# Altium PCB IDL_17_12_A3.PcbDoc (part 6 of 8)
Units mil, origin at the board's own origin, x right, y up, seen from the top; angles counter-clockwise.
Board outline 5119.97 x 10350 mil, 6 copper layers (Top Signal, 3.3 Volt, GND, 5 Volt, Split Plane, Bot Signal), stack 66.2 mil thick; 510 components, 178 nets, 2317 pads, 385 vias.
Unrouted connection lines stored in the file: 1.
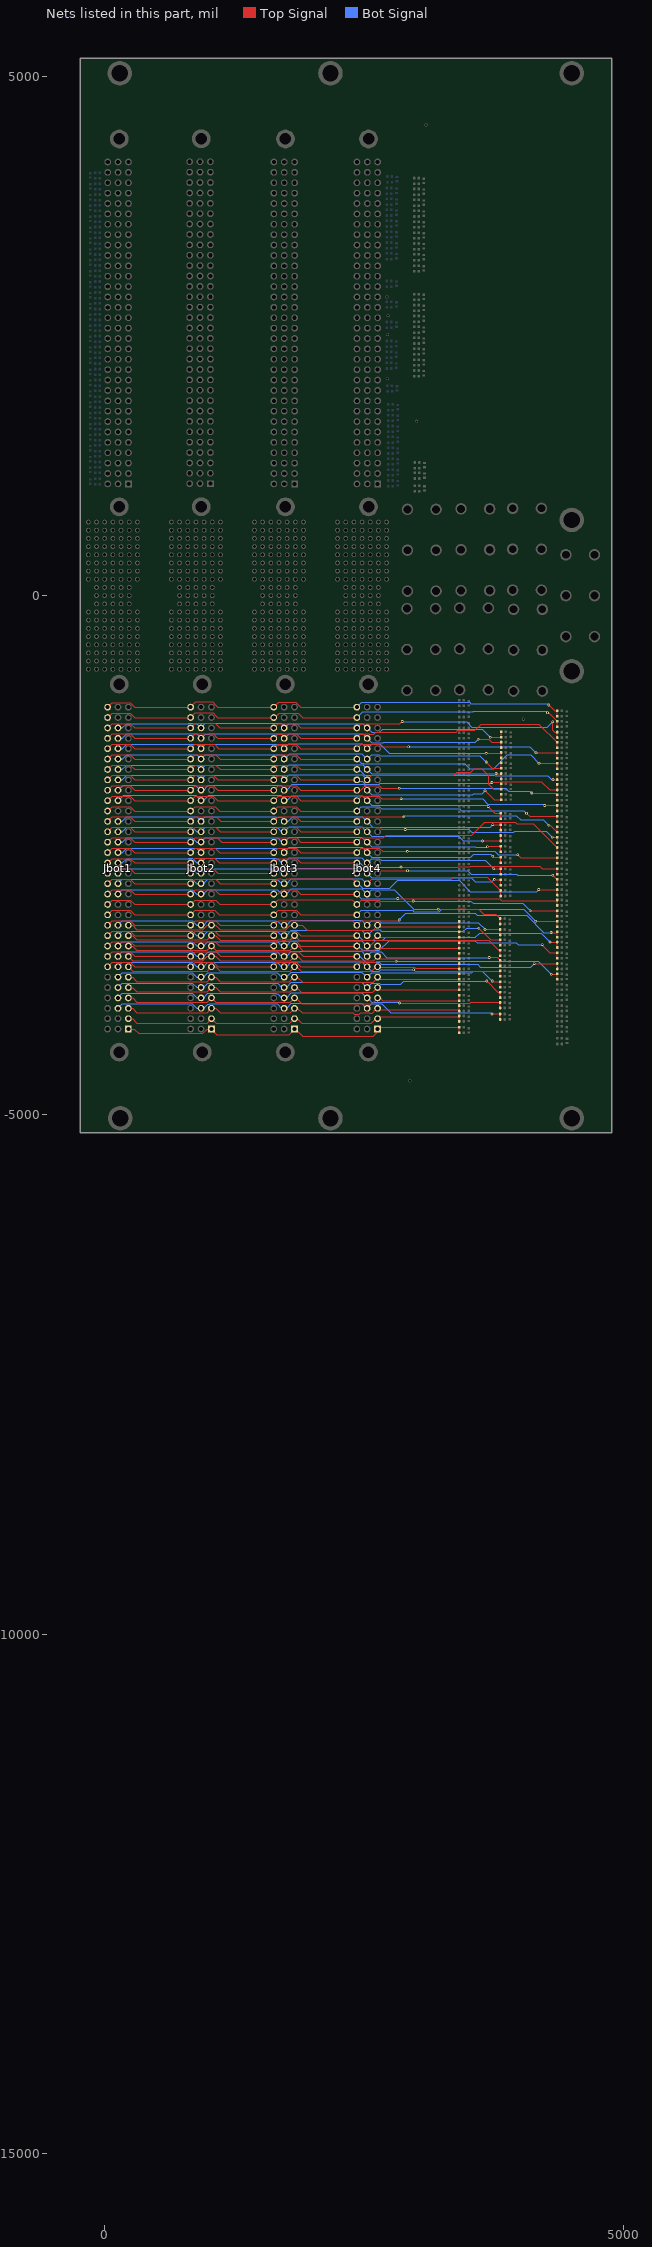
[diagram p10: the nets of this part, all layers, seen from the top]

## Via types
v1: diameter 25.59, hole 11.81, Top Signal to Bot Signal, 385 vias

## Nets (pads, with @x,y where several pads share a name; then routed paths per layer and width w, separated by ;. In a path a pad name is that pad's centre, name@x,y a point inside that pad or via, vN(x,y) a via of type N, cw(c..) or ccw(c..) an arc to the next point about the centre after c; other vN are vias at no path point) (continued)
JB22: Jbot1.A11 Jbot2.A11 Jbot3.A11 Jbot4.A11 R1RB_IDL_17_12_TerB22.1 R2RB_IDL_17_12_TerB22.2 | length 3346.2
  Top Signal w8: Jbot1.A11@228.26,-3173.77 228.68,-3173.35 268.12,-3173.35 310.6,-3215.83 945.79,-3215.83 988.27,-3173.35 Jbot2.A11@1028.19,-3173.35 1068.47,-3173.35 1111.37,-3216.25 1658.27,-3216.25 1658.55,-3215.97 1710.32,-3215.97 1710.59,-3216.25 1745.79,-3216.25 1788.27,-3173.77 Jbot3.A11@1828.19,-3173.77 1901.22,-3173.77 1949.03,-3221.58 2584.75,-3221.58 Jbot4.A11@2621.69,-3184.64 ; Jbot4.A11@2628.19,-3173.77 2644.59,-3190.17 R2RB_IDL_17_12_TerB22.2@3414.99,-3190.17 3414.99,-3164 3414.48,-3163.49 R1RB_IDL_17_12_TerB22.1@3414.48,-3137.31
JB23: Jbot1.A10 Jbot2.A10 Jbot3.A10 Jbot4.A10 R1RB_IDL_17_12_TerB23.1 R2RB_IDL_17_12_TerB23.2 | length 3421
  Top Signal w8: Jbot1.A10@228.26,-3273.77 268.54,-3273.77 310.6,-3315.83 985.71,-3315.83 Jbot2.A10@1028.19,-3273.35 1068.47,-3273.35 1111.37,-3316.25 1665.91,-3316.25 1666.19,-3315.97 1710.31,-3315.97 1710.59,-3316.25 1745.78,-3316.25 1746.06,-3315.97 1785.99,-3315.97 ; Jbot3.A10@1810.53,-3273.77 Jbot3.A10@1828.19,-3273.77 1785.99,-3315.97 ; Jbot3.A10@1828.19,-3277.46 1789.68,-3315.97 1785.99,-3315.97 ; Jbot3.A10@1828.19,-3277.42 1831.85,-3277.42 1874.33,-3319.9 2586.32,-3319.9 Jbot4.A10@2623.26,-3282.96 ; Jbot4.A10@2628.19,-3273.77 2644.59,-3290.17 R2RB_IDL_17_12_TerB23.2@3414.99,-3290.17 3414.99,-3264 3414.48,-3263.49 R1RB_IDL_17_12_TerB23.1@3414.48,-3237.31
JB24: Jbot1.A9 Jbot2.A9 Jbot3.A9 Jbot4.A9 R1RB_IDL_17_12_TerB24.1 R2RB_IDL_17_12_TerB24.2 | length 3352.2
  Top Signal w8: Jbot1.A9@228.26,-3373.77 268.54,-3373.77 310.6,-3415.83 985.71,-3415.83 Jbot2.A9@1028.19,-3373.35 1071.09,-3416.25 1645.79,-3416.25 1646.06,-3415.97 1710.32,-3415.97 1710.59,-3416.25 1745.79,-3416.25 1746.06,-3415.97 1785.99,-3415.97 Jbot3.A9@1828.19,-3373.77 ; Jbot3.A9@1826.41,-3375.74 1828.19,-3375.74 1866.68,-3375.74 1909.16,-3418.22 2589.47,-3418.22 Jbot4.A9@2626.41,-3381.28 ; Jbot4.A9@2628.19,-3373.77 2649.59,-3395.17 R2RB_IDL_17_12_TerB24.2@3414.99,-3395.17 3414.99,-3342.82 R1RB_IDL_17_12_TerB24.1@3414.48,-3342.31
JB25: Jbot1.A8 Jbot2.A8 Jbot3.A8 Jbot4.A8 R1RB_IDL_17_12_TerB25.1 R2RB_IDL_17_12_TerB25.2 | length 3346
  Top Signal w8: Jbot1.A8@228.26,-3473.77 271.86,-3517.37 859.07,-3517.37 860.61,-3515.83 945.79,-3515.83 988.27,-3473.35 Jbot2.A8@1028.19,-3473.35 1068.47,-3473.35 1111.37,-3516.25 1785.71,-3516.25 Jbot3.A8@1828.19,-3473.77 1857.7,-3473.77 1901.22,-3517.29 2590.29,-3517.29 Jbot4.A8@2622.47,-3485.11 ; Jbot4.A8@2628.19,-3473.77 2649.59,-3495.17 R2RB_IDL_17_12_TerB25.2@3414.99,-3495.17 3414.99,-3469 3414.48,-3468.49 R1RB_IDL_17_12_TerB25.1@3414.48,-3442.31
JB26: Jbot1.A7 Jbot2.A7 Jbot3.A7 Jbot4.A7 R1RB_IDL_17_12_TerB26.1 R2RB_IDL_17_12_TerB26.2 | length 3352.2
  Top Signal w8: Jbot1.A7@228.26,-3573.77 270.32,-3615.83 985.71,-3615.83 Jbot2.A7@1028.19,-3573.35 1068.47,-3573.35 1111.37,-3616.25 1786.21,-3616.25 ; 1786.21,-3615.75 Jbot3.A7@1828.19,-3573.77 ; Jbot3.A7@1811.46,-3573.17 1828.19,-3573.17 1851.74,-3573.17 1894.82,-3616.25 2573.92,-3616.25 Jbot4.A7@2611.46,-3578.71 ; Jbot4.A7@2628.19,-3573.77 2634.86,-3580.44 2984.33,-3580.44 2992.49,-3588.6 3408.42,-3588.6 R2RB_IDL_17_12_TerB26.2@3414.99,-3595.17 3414.99,-3569 3414.48,-3568.49 R1RB_IDL_17_12_TerB26.1@3414.48,-3542.31
JB27: Jbot1.A6 Jbot2.A6 Jbot3.A6 Jbot4.A6 R1RB_IDL_17_12_TerB27.1 R2RB_IDL_17_12_TerB27.2 | length 3349.5
  Top Signal w8: Jbot1.A6@228.26,-3673.77 268.54,-3673.77 310.6,-3715.83 985.71,-3715.83 Jbot2.A6@1028.19,-3673.35 1068.47,-3673.35 1111.37,-3716.25 1779.57,-3716.25 1822.05,-3673.77 Jbot3.A6@1828.19,-3673.77 1854.81,-3673.77 1905.23,-3724.19 2585.53,-3724.19 Jbot4.A6@2622.47,-3687.25 ; Jbot4.A6@2628.19,-3673.77 2649.59,-3695.17 R2RB_IDL_17_12_TerB27.2@3414.99,-3695.17 3414.99,-3669 3414.48,-3668.49 R1RB_IDL_17_12_TerB27.1@3414.48,-3642.31
JB28: Jbot1.A5 Jbot2.A5 Jbot3.A5 Jbot4.A5 R1RB_IDL_17_12_TerB28.1 R2RB_IDL_17_12_TerB28.2 | length 3348.9
  Top Signal w8: Jbot1.A5@228.26,-3773.77 268.54,-3773.77 310.6,-3815.83 985.71,-3815.83 Jbot2.A5@1028.19,-3773.35 1068.47,-3773.35 1111.37,-3816.25 1785.71,-3816.25 Jbot3.A5@1823.5,-3778.46 ; Jbot3.A5@1814.61,-3778.46 Jbot3.A5@1823.5,-3778.46 ; Jbot3.A5@1828.19,-3773.77 Jbot3.A5@1823.5,-3778.46 ; Jbot4.A5@2614.61,-3784 2581.38,-3817.23 1893.66,-3817.23 1854.88,-3778.46 1828.19,-3778.46 Jbot3.A5@1823.5,-3778.46 ; Jbot4.A5@2628.19,-3773.77 2649.59,-3795.17 R2RB_IDL_17_12_TerB28.2@3414.99,-3795.17 3414.99,-3769 3414.48,-3768.49 R1RB_IDL_17_12_TerB28.1@3414.48,-3742.31
JB29: Jbot1.A4 Jbot2.A4 Jbot3.A4 Jbot4.A4 R1RB_IDL_17_12_TerB29.1 R2RB_IDL_17_12_TerB29.2 | length 3354
  Top Signal w8: Jbot1.A4@228.26,-3873.77 268.54,-3873.77 310.6,-3915.83 985.71,-3915.83 Jbot2.A4@1028.19,-3873.35 1071.09,-3916.25 1785.71,-3916.25 Jbot3.A4@1816.53,-3885.43 ; Jbot3.A4@1813.82,-3885.43 Jbot3.A4@1816.53,-3885.43 ; Jbot3.A4@1828.19,-3873.77 Jbot3.A4@1816.53,-3885.43 ; Jbot4.A4@2613.82,-3890.97 2576.88,-3927.91 1896.58,-3927.91 1854.1,-3885.43 1828.19,-3885.43 Jbot3.A4@1816.53,-3885.43 ; Jbot4.A4@2628.19,-3873.77 2652.24,-3873.77 2678.64,-3900.17 R2RB_IDL_17_12_TerB29.2@3414.99,-3900.17 3414.99,-3874 3414.48,-3873.49 R1RB_IDL_17_12_TerB29.1@3414.48,-3847.31
JB30: Jbot1.A3 Jbot2.A3 Jbot3.A3 Jbot4.A3 R1RB_IDL_17_12_TerB30.1 R2RB_IDL_17_12_TerB30.2 | length 3373.1
  Top Signal w8: Jbot1.A3@228.26,-3973.77 268.54,-3973.77 310.6,-4015.83 985.71,-4015.83 Jbot2.A3@1028.19,-3973.35 1068.47,-3973.35 1111.37,-4016.25 1645.79,-4016.25 1647.24,-4014.79 1709.14,-4014.79 1710.59,-4016.25 1785.71,-4016.25 Jbot3.A3@1828.19,-3973.77 ; Jbot3.A3@1816.18,-3971.95 1828.19,-3971.95 1856.46,-3971.95 1901.8,-4017.29 2391.51,-4017.29 2405.51,-4031.29 2450.87,-4031.29 2464.87,-4017.29 2551.58,-4017.29 2553.27,-4018.98 2574.69,-4018.98 Jbot4.A3@2616.18,-3977.49 ; Jbot4.A3@2628.19,-3973.77 2641.29,-3986.87 3398.93,-3986.87 3413.61,-4001.55 3414.48,-4002.42 3414.48,-4000.17 R1RB_IDL_17_12_TerB30.1@3414.48,-3947.31
JB31: Jbot1.A2 Jbot2.A2 Jbot3.A2 Jbot4.A2 R1RB_IDL_17_12_TerB31.1 R2RB_IDL_17_12_TerB31.2 | length 3359.2
  Top Signal w8: Jbot1.A2@228.26,-4073.77 268.54,-4073.77 310.6,-4115.83 985.71,-4115.83 Jbot2.A2@1028.19,-4073.35 1072.13,-4117.29 1784.67,-4117.29 Jbot3.A2@1828.19,-4073.77 ; Jbot3.A2@1809.89,-4071.05 1828.19,-4071.05 1850.17,-4071.05 1896.4,-4117.29 2391.51,-4117.29 2393.61,-4119.39 2567.09,-4119.39 Jbot4.A2@2609.89,-4076.59 ; Jbot4.A2@2628.19,-4073.77 2647,-4054.96 3406.83,-4054.96 R1RB_IDL_17_12_TerB31.1@3414.48,-4047.31 3414.48,-4073.49 3414.99,-4074 R2RB_IDL_17_12_TerB31.2@3414.99,-4100.17
JB32: Jbot1.A1 Jbot2.A1 Jbot3.A1 Jbot4.A1 R1RB_IDL_17_12_TerB32.1 R2RB_IDL_17_12_TerB32.2 | length 3365.2
  Top Signal w8: Jbot1.A1@228.26,-4173.77 228.68,-4173.35 287.14,-4173.35 329.62,-4215.83 945.79,-4215.83 988.27,-4173.35 Jbot2.A1@1028.19,-4173.35 1081.65,-4226.8 1775.15,-4226.8 Jbot3.A1@1828.19,-4173.77 1838.04,-4173.77 1906.8,-4242.53 2587.11,-4242.53 Jbot4.A1@2624.05,-4205.59 ; Jbot4.A1@2628.19,-4173.77 2645.58,-4156.37 R1RB_IDL_17_12_TerB32.1@3414.08,-4156.37 3414.08,-4183.49 3414.59,-4184 R2RB_IDL_17_12_TerB32.2@3414.59,-4209.23
JB33: Jbot1.B30 Jbot2.B30 Jbot3.B30 Jbot4.B30 R1RB_IDL_17_12_TerB33.1 R2RB_IDL_17_12_TerB33.2 | length 3931.8
  Top Signal w8: v1(3713.46,-1362.75) R2RB_IDL_17_12_TerB33.2@3818.94,-1362.75 3818.94,-1337.23 3818.43,-1336.72 R1RB_IDL_17_12_TerB33.1@3818.43,-1309.89
  Bot Signal w8: Jbot1.B30@128.26,-1273.77 168.18,-1273.77 210.66,-1231.29 810.17,-1231.29 810.59,-1230.87 845.79,-1230.87 846.21,-1231.29 886.13,-1231.29 Jbot2.B30@928.19,-1273.35 970.67,-1230.87 1702.32,-1230.87 Jbot3.B30@1736.7,-1265.25 ; Jbot3.B30@1728.19,-1273.77 Jbot3.B30@1736.7,-1265.25 ; Jbot3.B30@1747.6,-1276.15 Jbot3.B30@1736.7,-1265.25 ; v1(3713.46,-1362.75) 3636.95,-1286.23 2675.8,-1286.23 2645.79,-1316.25 2570.67,-1316.25 Jbot4.B30@2528.19,-1273.77 2485.71,-1231.29 1770.67,-1231.29 Jbot3.B30@1736.7,-1265.25
JB34: Jbot1.B29 Jbot2.B29 Jbot3.B29 Jbot4.B29 R1RB_IDL_17_12_TerB34.1 R2RB_IDL_17_12_TerB34.2 | length 3900.6
  Top Signal w8: v1(3595.9,-1382.59) 3698.31,-1382.59 3725.61,-1409.89 R1RB_IDL_17_12_TerB34.1@3818.43,-1409.89 3818.43,-1436.72 3818.94,-1437.23 R2RB_IDL_17_12_TerB34.2@3818.94,-1462.75
  Bot Signal w8: Jbot1.B29@128.26,-1373.77 168.18,-1373.77 210.66,-1331.29 810.17,-1331.29 810.59,-1330.87 845.79,-1330.87 846.21,-1331.29 886.13,-1331.29 Jbot2.B29@928.19,-1373.35 967.45,-1334.09 1007.37,-1334.09 1010.59,-1330.87 1702.32,-1330.87 1736.7,-1365.25 Jbot3.B29@1737.89,-1366.44 ; Jbot3.B29@1728.19,-1373.77 1730.57,-1373.77 Jbot3.B29@1737.89,-1366.44 ; v1(3595.9,-1382.59) 3569.09,-1409.41 2687.15,-1409.41 2680.32,-1416.25 2570.67,-1416.25 Jbot4.B29@2528.19,-1373.77 2483.41,-1328.98 1775.35,-1328.98 Jbot3.B29@1737.89,-1366.44
JB35: Jbot1.B28 Jbot2.B28 Jbot3.B28 Jbot4.B28 R1RB_IDL_17_12_TerB35.1 R2RB_IDL_17_12_TerB35.2 | length 3917.6
  Top Signal w8: v1(3675.37,-1518.85) 3809.47,-1518.85 R1RB_IDL_17_12_TerB35.1@3818.43,-1509.89 3818.43,-1536.72 3818.94,-1537.23 R2RB_IDL_17_12_TerB35.2@3818.94,-1562.75
  Bot Signal w8: Jbot1.B28@128.26,-1473.77 168.18,-1473.77 210.66,-1431.29 810.17,-1431.29 810.59,-1430.87 845.79,-1430.87 846.21,-1431.29 886.13,-1431.29 Jbot2.B28@928.19,-1473.35 970.67,-1430.87 1645.36,-1430.87 1648.58,-1434.09 1705.54,-1434.09 Jbot3.B28@1734.67,-1463.22 ; Jbot3.B28@1728.19,-1473.77 1728.19,-1469.7 Jbot3.B28@1734.67,-1463.22 ; v1(3675.37,-1518.85) 2740.18,-1518.85 2651.58,-1430.25 2571.71,-1430.25 Jbot4.B28@2528.19,-1473.77 2479.01,-1424.59 1773.3,-1424.59 Jbot3.B28@1734.67,-1463.22
JB36: Jbot1.B27 Jbot2.B27 Jbot3.B27 Jbot4.B27 R1RB_IDL_17_12_TerB36.1 R2RB_IDL_17_12_TerB36.2 | length 3936.3
  Top Signal w8: v1(3673.33,-1602.57) 3733.51,-1662.75 R2RB_IDL_17_12_TerB36.2@3818.94,-1662.75 3818.94,-1637.23 3818.43,-1636.72 R1RB_IDL_17_12_TerB36.1@3818.43,-1609.89
  Bot Signal w8: Jbot1.B27@128.26,-1573.77 168.18,-1573.77 210.66,-1531.29 810.17,-1531.29 810.59,-1530.87 845.79,-1530.87 846.21,-1531.29 886.13,-1531.29 Jbot2.B27@928.19,-1573.35 970.67,-1530.87 1645.36,-1530.87 1648.58,-1534.09 1705.54,-1534.09 1736.7,-1565.25 Jbot3.B27@1738.96,-1567.51 ; Jbot3.B27@1728.19,-1573.77 1732.71,-1573.77 Jbot3.B27@1738.96,-1567.51 ; v1(3673.33,-1602.57) 3613.96,-1543.2 2657.7,-1543.2 2645.79,-1531.29 2570.67,-1531.29 Jbot4.B27@2528.19,-1573.77 2478.03,-1523.61 1782.86,-1523.61 Jbot3.B27@1738.96,-1567.51
JB37: Jbot1.B26 Jbot2.B26 Jbot3.B26 Jbot4.B26 R1RB_IDL_17_12_TerB37.1 R2RB_IDL_17_12_TerB37.2 | length 3878.4
  Top Signal w8: v1(3769.41,-1712.89) R1RB_IDL_17_12_TerB37.1@3818.43,-1712.89 3818.43,-1739.72 3818.94,-1740.23 R2RB_IDL_17_12_TerB37.2@3818.94,-1765.75
  Bot Signal w8: Jbot1.B26@128.26,-1673.77 168.18,-1673.77 210.66,-1631.29 810.17,-1631.29 810.59,-1630.87 845.79,-1630.87 846.21,-1631.29 886.13,-1631.29 Jbot2.B26@928.19,-1673.35 967.45,-1634.09 1007.37,-1634.09 1010.59,-1630.87 1702.32,-1630.87 1736.7,-1665.25 Jbot3.B26@1739.16,-1667.7 ; Jbot3.B26@1728.19,-1673.77 1733.1,-1673.77 Jbot3.B26@1739.16,-1667.7 ; v1(3769.41,-1712.89) 3769.1,-1713.2 3602.64,-1713.2 3601.56,-1714.28 3582.68,-1714.28 3581.61,-1713.2 2648.83,-1713.2 2645.79,-1716.25 2570.67,-1716.25 Jbot4.B26@2528.19,-1673.77 2484.57,-1630.14 1776.72,-1630.14 Jbot3.B26@1739.16,-1667.7
JB38: Jbot1.B25 Jbot2.B25 Jbot3.B25 Jbot4.B25 R1RB_IDL_17_12_TerB38.1 R2RB_IDL_17_12_TerB38.2 | length 4055.4
  Top Signal w8: Jbot4.B25@2528.19,-1773.77 2571.71,-1730.25 3363.75,-1730.25 3394,-1700 3527,-1700 3560,-1667 3630.02,-1667 3699.4,-1736.38 3699.4,-1816.9 3748.25,-1865.75 R2RB_IDL_17_12_TerB38.2@3818.94,-1865.75 3818.94,-1840.23 3818.43,-1839.72 R1RB_IDL_17_12_TerB38.1@3818.43,-1812.89 R1RB_IDL_17_12_TerB38.1@3812.84,-1818.47
  Bot Signal w8: Jbot1.B25@128.26,-1773.77 168.18,-1773.77 211.08,-1730.87 845.79,-1730.87 846.63,-1731.71 886.56,-1731.71 Jbot2.B25@928.19,-1773.35 970.67,-1730.87 1702.32,-1730.87 Jbot3.B25@1736.7,-1765.25 ; Jbot3.B25@1728.19,-1773.77 Jbot3.B25@1736.7,-1765.25 ; Jbot3.B25@1747.6,-1776.15 Jbot3.B25@1736.7,-1765.25 ; Jbot4.B25@2528.19,-1773.77 2481.16,-1726.74 1775.22,-1726.74 Jbot3.B25@1736.7,-1765.25
JB39: Jbot1.B24 Jbot2.B24 Jbot3.B24 Jbot4.B24 R1RB_IDL_17_12_TerB39.1 R2RB_IDL_17_12_TerB39.2 | length 3934.5
  Top Signal w8: v1(3662.95,-1878.23) 3750.46,-1965.75 R2RB_IDL_17_12_TerB39.2@3818.94,-1965.75 3818.94,-1940.23 3818.43,-1939.72 R1RB_IDL_17_12_TerB39.1@3818.43,-1912.89
  Bot Signal w8: Jbot1.B24@128.26,-1873.77 177.27,-1824.76 874.23,-1824.76 922.82,-1873.35 Jbot2.B24@928.19,-1873.35 ; Jbot2.B24@947.67,-1876.57 996.68,-1827.55 1693.64,-1827.55 1734.02,-1867.94 1742.23,-1876.15 Jbot3.B24@1747.6,-1876.15 ; Jbot3.B24@1756.27,-1867.32 1805.28,-1818.31 2492.85,-1818.31 2538.25,-1863.7 2541.45,-1866.9 Jbot4.B24@2556.2,-1866.9 ; Jbot4.B24@2528.19,-1873.77 2570.67,-1916.25 3545.64,-1916.25 3554.48,-1907.4 3633.78,-1907.4 v1(3662.95,-1878.23)
JB40: Jbot1.B23 Jbot2.B23 Jbot3.B23 Jbot4.B23 R1RB_IDL_17_12_TerB40.1 R2RB_IDL_17_12_TerB40.2 | length 3914.2
  Top Signal w8: v1(3693.95,-2031.23) 3757.26,-2094.54 R1RB_IDL_17_12_TerB40.1@3813.43,-2094.54 3813.43,-2120.72 3813.94,-2121.23 R2RB_IDL_17_12_TerB40.2@3813.94,-2147.4
  Bot Signal w8: Jbot1.B23@128.26,-1973.77 131.98,-1973.77 185.14,-1920.6 875.44,-1920.6 Jbot2.B23@928.19,-1973.35 ; Jbot2.B23@947.67,-1976.57 951.38,-1976.57 1004.55,-1923.4 1694.85,-1923.4 1736.7,-1965.25 Jbot3.B23@1745.22,-1973.77 ; Jbot3.B23@1728.19,-1973.77 Jbot3.B23@1745.22,-1973.77 ; v1(3693.95,-2031.23) 3681.99,-2019.28 2653.58,-2019.28 2651.58,-2017.29 2604.8,-2017.29 2602.8,-2019.28 2573.7,-2019.28 Jbot4.B23@2528.19,-1973.77 2479.95,-1925.52 1801.78,-1925.52 1753.54,-1973.77 Jbot3.B23@1745.22,-1973.77
JB41: Jbot1.B21 Jbot2.B21 Jbot3.B21 Jbot4.B21 R1RB_IDL_17_12_TerB41.1 R2RB_IDL_17_12_TerB41.2 | length 3897.4
  Top Signal w8: v1(3737.06,-2204.54) R1RB_IDL_17_12_TerB41.1@3813.43,-2204.54 3813.43,-2230.72 3813.94,-2231.23 R2RB_IDL_17_12_TerB41.2@3813.94,-2257.4
  Bot Signal w8: Jbot1.B21@128.26,-2173.77 168.18,-2173.77 210.66,-2131.29 810.17,-2131.29 810.59,-2130.87 885.71,-2130.87 Jbot2.B21@928.19,-2173.35 970.67,-2130.87 1645.36,-2130.87 1648.16,-2133.67 1705.12,-2133.67 1736.7,-2165.25 Jbot3.B21@1745.22,-2173.77 ; Jbot3.B21@1728.19,-2173.77 Jbot3.B21@1745.22,-2173.77 ; Jbot3.B21@1747.6,-2176.15 Jbot3.B21@1745.22,-2173.77 ; v1(3737.06,-2204.54) 3712.85,-2228.76 3554.8,-2228.76 3554.73,-2228.69 2583.11,-2228.69 Jbot4.B21@2528.19,-2173.77 2523.95,-2173.77 2481.47,-2131.29 1810.59,-2131.29 1768.11,-2173.77 Jbot3.B21@1745.22,-2173.77
JB42: Jbot1.B20 Jbot2.B20 Jbot3.B20 Jbot4.B20 R1RB_IDL_17_12_TerB42.1 R2RB_IDL_17_12_TerB42.2 | length 3936.9
  Top Signal w8: v1@3634.12,-2362.4 v1(3638.93,-2362.4) R2RB_IDL_17_12_TerB42.2@3813.94,-2362.4 3813.94,-2336.23 3813.43,-2335.72 R1RB_IDL_17_12_TerB42.1@3813.43,-2309.54
  Bot Signal w8: Jbot1.B20@128.26,-2273.77 168.18,-2273.77 210.66,-2231.29 810.17,-2231.29 810.59,-2230.87 845.79,-2230.87 888.27,-2273.35 Jbot2.B20@928.19,-2273.35 970.67,-2230.87 1662.39,-2230.87 1707.67,-2276.15 1728.19,-2276.15 Jbot3.B20@1747.6,-2276.15 ; Jbot3.B20@1728.19,-2273.77 1777.12,-2224.84 2438.18,-2224.84 ; 2438.6,-2224.42 2473.8,-2224.42 2516.28,-2266.9 2528.19,-2266.9 Jbot4.B20@2556.2,-2266.9 ; Jbot4.B20@2528.19,-2273.77 2571.42,-2317 3410,-2317 3455.4,-2362.4 v1(3638.93,-2362.4)
JB43: Jbot1.B19 Jbot2.B19 Jbot3.B19 Jbot4.B19 R1RB_IDL_17_12_TerB43.1 R2RB_IDL_17_12_TerB43.2 | length 3916.9
  Top Signal w8: v1(3685.78,-2417.56) 3688.79,-2414.54 R1RB_IDL_17_12_TerB43.1@3813.43,-2414.54 3813.43,-2440.72 3813.94,-2441.23 R2RB_IDL_17_12_TerB43.2@3813.94,-2467.4
  Bot Signal w8: Jbot1.B19@128.26,-2373.77 168.18,-2373.77 210.66,-2331.29 810.17,-2331.29 810.59,-2330.87 845.79,-2330.87 888.27,-2373.35 Jbot2.B19@928.19,-2373.35 970.67,-2330.87 1645.36,-2330.87 1648.16,-2333.67 1665.19,-2333.67 1707.67,-2376.15 1728.19,-2376.15 Jbot3.B19@1747.6,-2376.15 ; Jbot3.B19@1728.19,-2373.77 1777.12,-2324.84 2438.18,-2324.84 ; 2438.6,-2324.42 2473.8,-2324.42 2516.28,-2366.9 2528.19,-2366.9 Jbot4.B19@2556.2,-2366.9 ; Jbot4.B19@2528.19,-2373.77 2571.42,-2417 3569.86,-2417 3573.63,-2420.76 3682.57,-2420.76 v1(3685.78,-2417.56)
JB44: Jbot1.B18 Jbot2.B18 Jbot3.B18 Jbot4.B18 R1RB_IDL_17_12_TerB44.1 R2RB_IDL_17_12_TerB44.2 | length 3896
  Top Signal w8: v1(3737.1,-2508.99) 3747.65,-2519.54 R1RB_IDL_17_12_TerB44.1@3813.43,-2519.54 3813.43,-2545.72 3813.94,-2546.23 R2RB_IDL_17_12_TerB44.2@3813.94,-2572.4
  Bot Signal w8: Jbot1.B18@128.26,-2473.77 168.18,-2473.77 210.66,-2431.29 810.17,-2431.29 810.59,-2430.87 845.79,-2430.87 846.21,-2431.29 886.13,-2431.29 Jbot2.B18@928.19,-2473.35 967.45,-2434.09 1007.37,-2434.09 1010.59,-2430.87 1702.32,-2430.87 Jbot3.B18@1736.7,-2465.25 ; Jbot3.B18@1728.19,-2473.77 Jbot3.B18@1736.7,-2465.25 ; 2438.18,-2424.84 1777.12,-2424.84 Jbot3.B18@1736.7,-2465.25 ; 2438.6,-2424.42 2473.8,-2424.42 ; 2474.22,-2424.84 2479.26,-2424.84 Jbot4.B18@2528.19,-2473.77 2571.71,-2517.28 3524.72,-2517.28 3553,-2489 3717.1,-2489 v1(3737.1,-2508.99)
JB45: Jbot1.B17 Jbot2.B17 Jbot3.B17 Jbot4.B17 R1RB_IDL_17_12_TerB45.1 R2RB_IDL_17_12_TerB45.2 | length 3913.2
  Top Signal w8: v1(3746.62,-2629.54) R1RB_IDL_17_12_TerB45.1@3813.43,-2629.54 3813.43,-2655.72 3813.94,-2656.23 R2RB_IDL_17_12_TerB45.2@3813.94,-2682.4
  Bot Signal w8: Jbot1.B17@128.26,-2573.77 168.18,-2573.77 210.66,-2531.29 810.17,-2531.29 810.59,-2530.87 845.79,-2530.87 888.27,-2573.35 Jbot2.B17@928.19,-2573.35 970.67,-2530.87 1645.36,-2530.87 1648.16,-2533.67 1665.19,-2533.67 1707.67,-2576.15 1728.19,-2576.15 Jbot3.B17@1747.6,-2576.15 ; Jbot3.B17@1728.19,-2573.77 1777.12,-2524.84 2438.18,-2524.84 ; 2438.6,-2524.42 2473.8,-2524.42 Jbot4.B17@2516.28,-2566.9 ; Jbot4.B17@2528.19,-2573.77 2570.67,-2531.29 2645.79,-2531.29 2663.24,-2548.74 3665.82,-2548.74 v1(3746.62,-2629.54)
JB46: Jbot1.B16 Jbot2.B16 Jbot3.B16 Jbot4.B16 R1RB_IDL_17_12_TerB46.1 R2RB_IDL_17_12_TerB46.2 | length 3891.4
  Top Signal w8: v1(3753.11,-2732.44) 3755.22,-2734.54 R1RB_IDL_17_12_TerB46.1@3813.43,-2734.54 3813.43,-2760.72 3813.94,-2761.23 R2RB_IDL_17_12_TerB46.2@3813.94,-2787.4
  Bot Signal w8: Jbot1.B16@128.26,-2673.77 171.16,-2630.87 845.79,-2630.87 888.27,-2673.35 Jbot2.B16@928.19,-2673.35 ; Jbot2.B16@947.67,-2676.57 990.57,-2633.67 1007.79,-2633.67 1010.59,-2630.87 1662.39,-2630.87 1707.67,-2676.15 1728.19,-2676.15 Jbot3.B16@1747.6,-2676.15 ; Jbot3.B16@1756.27,-2667.32 1799.17,-2624.42 2473.8,-2624.42 2516.28,-2666.9 2528.19,-2666.9 Jbot4.B16@2556.2,-2666.9 ; Jbot4.B16@2528.19,-2673.77 2571.71,-2717.28 3531.64,-2717.28 3569.98,-2755.62 3582.02,-2755.62 3582.68,-2756.28 3729.27,-2756.28 v1(3753.11,-2732.44)
JB47: Jbot1.B15 Jbot2.B15 Jbot3.B15 Jbot4.B15 R1RB_IDL_17_12_TerB47.1 R2RB_IDL_17_12_TerB47.2 | length 3926
  Top Signal w8: Jbot4.B15@2528.19,-2773.77 2571.71,-2730.25 3339.75,-2730.25 3359,-2711 3582.37,-2711 3582.68,-2710.69 3601.56,-2710.69 3601.88,-2711 3684.88,-2711 R1RB_IDL_17_12_TerB47.1@3813.43,-2839.54 3813.43,-2865.72 3813.94,-2866.23 R2RB_IDL_17_12_TerB47.2@3813.94,-2892.4
  Bot Signal w8: Jbot1.B15@128.26,-2773.77 171.16,-2730.87 845.79,-2730.87 888.27,-2773.35 Jbot2.B15@928.19,-2773.35 ; Jbot2.B15@947.67,-2776.57 993.37,-2730.87 1645.36,-2730.87 1648.16,-2733.67 1665.19,-2733.67 1707.67,-2776.15 1728.19,-2776.15 Jbot3.B15@1747.6,-2776.15 ; Jbot3.B15@1756.27,-2767.32 1799.17,-2724.42 2473.8,-2724.42 2516.28,-2766.9 2528.19,-2766.9 Jbot4.B15@2556.2,-2766.9
JB48: Jbot1.B14 Jbot2.B14 Jbot3.B14 Jbot4.B14 R1RB_IDL_17_12_TerB48.1 R2RB_IDL_17_12_TerB48.2 | length 3937.4
  Top Signal w8: v1(3211.55,-3019.26) 3399.24,-3019.26 3401.98,-3016.51 3470.39,-3016.51 3473.02,-3019.15 3603.82,-3019.15 3651.13,-3066.45 3765.33,-3066.45 R1RB_IDL_17_12_TerB48.1@3808.43,-3109.54 3808.43,-3135.72 3808.94,-3136.23 R2RB_IDL_17_12_TerB48.2@3808.94,-3162.4
  Bot Signal w8: Jbot1.B14@128.26,-2873.77 171.16,-2830.87 845.79,-2830.87 888.27,-2873.35 Jbot2.B14@928.19,-2873.35 ; Jbot2.B14@947.67,-2876.57 990.57,-2833.67 1007.79,-2833.67 1010.59,-2830.87 1662.39,-2830.87 1707.67,-2876.15 1728.19,-2876.15 Jbot3.B14@1747.6,-2876.15 ; Jbot3.B14@1756.27,-2867.32 1799.17,-2824.42 2473.8,-2824.42 Jbot4.B14@2516.28,-2866.9 ; Jbot4.B14@2528.19,-2873.77 2569.87,-2832.08 2609.8,-2832.08 2610.59,-2831.29 2645.79,-2831.29 2646.58,-2832.08 2752.91,-2832.08 2753.71,-2831.29 2787.48,-2831.29 2975.46,-3019.26 v1(3211.55,-3019.26)
JB49: Jbot1.B11 Jbot2.B11 Jbot3.B11 Jbot4.B11 R1RB_IDL_17_12_TerB49.1 R2RB_IDL_17_12_TerB49.2 | length 3872.5
  Top Signal w8: v1(3663.26,-3214.54) R1RB_IDL_17_12_TerB49.1@3808.43,-3214.54 3808.43,-3240.72 3808.94,-3241.23 R2RB_IDL_17_12_TerB49.2@3808.94,-3267.4
  Bot Signal w8: Jbot1.B11@128.26,-3173.77 171.16,-3130.87 845.79,-3130.87 888.27,-3173.35 Jbot2.B11@928.19,-3173.35 ; Jbot2.B11@947.67,-3176.57 993.37,-3130.87 1645.36,-3130.87 1648.16,-3133.67 1665.19,-3133.67 1707.67,-3176.15 1728.19,-3176.15 Jbot3.B11@1747.6,-3176.15 ; Jbot3.B11@1756.27,-3167.32 1799.17,-3124.42 2473.8,-3124.42 2516.28,-3166.9 2528.19,-3166.9 Jbot4.B11@2535.06,-3166.9 ; Jbot4.B11@2528.19,-3173.77 Jbot4.B11@2535.06,-3166.9 ; v1(3663.26,-3214.54) 3599.69,-3150.98 2665.48,-3150.98 2645.79,-3131.29 2570.67,-3131.29 Jbot4.B11@2535.06,-3166.9
JB50: Jbot1.B10 Jbot2.B10 Jbot3.B10 Jbot4.B10 R1RB_IDL_17_12_TerB50.1 R2RB_IDL_17_12_TerB50.2 | length 3890.4
  Top Signal w8: v1(3603.95,-3202.23) 3716.26,-3314.54 R1RB_IDL_17_12_TerB50.1@3808.43,-3314.54 3808.43,-3340.72 3808.94,-3341.23 R2RB_IDL_17_12_TerB50.2@3808.94,-3367.4
  Bot Signal w8: Jbot1.B10@128.26,-3273.77 171.16,-3230.87 845.79,-3230.87 888.27,-3273.35 Jbot2.B10@928.19,-3273.35 ; Jbot2.B10@947.67,-3276.57 990.57,-3233.67 1007.79,-3233.67 1010.59,-3230.87 1662.39,-3230.87 1707.67,-3276.15 1728.19,-3276.15 Jbot3.B10@1747.6,-3276.15 ; Jbot3.B10@1756.27,-3267.32 1799.17,-3224.42 2473.8,-3224.42 Jbot4.B10@2516.28,-3266.9 ; Jbot4.B10@2528.19,-3273.77 2584.67,-3217.29 2651.58,-3217.29 2665.3,-3231 3455,-3231 3485.38,-3200.62 3602.33,-3200.62 v1(3603.95,-3202.23)
JB51: Jbot1.B9 Jbot2.B9 Jbot3.B9 Jbot4.B9 R1RB_IDL_17_12_TerB51.1 R2RB_IDL_17_12_TerB51.2 | length 3906.1
  Top Signal w8: Jbot4.B9@2528.19,-3373.77 2552.25,-3373.77 2609.77,-3316.25 3698.16,-3316.25 3796.46,-3414.54 R1RB_IDL_17_12_TerB51.1@3808.43,-3414.54 3808.43,-3466.89 R2RB_IDL_17_12_TerB51.2@3808.94,-3467.4
  Bot Signal w8: Jbot1.B9@128.26,-3373.77 171.16,-3330.87 845.79,-3330.87 888.27,-3373.35 Jbot2.B9@928.19,-3373.35 ; Jbot2.B9@947.67,-3376.57 993.37,-3330.87 1645.36,-3330.87 1648.16,-3333.67 1665.19,-3333.67 1707.67,-3376.15 1728.19,-3376.15 Jbot3.B9@1747.6,-3376.15 ; Jbot3.B9@1756.27,-3367.32 1799.17,-3324.42 2473.8,-3324.42 2516.28,-3366.9 2528.19,-3366.9 Jbot4.B9@2556.2,-3366.9
JB52: Jbot1.B8 Jbot2.B8 Jbot3.B8 Jbot4.B8 R1RB_IDL_17_12_TerB52.1 R2RB_IDL_17_12_TerB52.2 | length 3873.2
  Top Signal w8: v1(3702.71,-3484.23) 3780.12,-3484.23 R1RB_IDL_17_12_TerB52.1@3808.43,-3512.54 3808.43,-3538.72 3808.94,-3539.23 R2RB_IDL_17_12_TerB52.2@3808.94,-3565.4
  Bot Signal w8: Jbot1.B8@128.26,-3473.77 171.16,-3430.87 845.79,-3430.87 888.27,-3473.35 Jbot2.B8@928.19,-3473.35 ; Jbot2.B8@947.67,-3476.57 990.57,-3433.67 1007.79,-3433.67 1010.59,-3430.87 1662.39,-3430.87 1707.67,-3476.15 1728.19,-3476.15 Jbot3.B8@1747.6,-3476.15 ; Jbot3.B8@1756.27,-3467.32 1799.17,-3424.42 2473.8,-3424.42 2516.28,-3466.9 2528.19,-3466.9 Jbot4.B8@2535.06,-3466.9 ; Jbot4.B8@2528.19,-3473.77 Jbot4.B8@2535.06,-3466.9 ; v1(3702.71,-3484.23) 3700.83,-3486.11 2718.46,-3486.11 2663.64,-3431.29 2570.67,-3431.29 Jbot4.B8@2535.06,-3466.9
JB53: Jbot1.B7 Jbot2.B7 Jbot3.B7 Jbot4.B7 R1RB_IDL_17_12_TerB53.1 R2RB_IDL_17_12_TerB53.2 | length 3873.4
  Top Signal w8: v1(2974.89,-3603.23) 2990.34,-3618.69 2991.06,-3617.96 3803.01,-3617.96 R1RB_IDL_17_12_TerB53.1@3808.43,-3612.54 3808.43,-3638.72 3808.94,-3639.23 R2RB_IDL_17_12_TerB53.2@3808.94,-3665.4
  Bot Signal w8: Jbot1.B7@128.26,-3573.77 171.16,-3530.87 845.79,-3530.87 888.27,-3573.35 Jbot2.B7@928.19,-3573.35 ; Jbot2.B7@947.67,-3576.57 993.37,-3530.87 1645.36,-3530.87 1648.16,-3533.67 1665.19,-3533.67 1707.67,-3576.15 1728.19,-3576.15 Jbot3.B7@1747.6,-3576.15 ; Jbot3.B7@1756.27,-3567.32 1799.17,-3524.42 2473.8,-3524.42 2516.28,-3566.9 2528.19,-3566.9 Jbot4.B7@2556.2,-3566.9 ; Jbot4.B7@2528.19,-3573.77 2570.67,-3616.25 2645.79,-3616.25 2658.8,-3603.23 v1(2974.89,-3603.23)
JB54: Jbot1.B6 Jbot2.B6 Jbot3.B6 Jbot4.B6 R1RB_IDL_17_12_TerB54.1 R2RB_IDL_17_12_TerB54.2 | length 3885.1
  Top Signal w8: v1(3731.88,-3710.48) 3738.95,-3717.54 R1RB_IDL_17_12_TerB54.1@3808.43,-3717.54 3808.43,-3743.72 3808.94,-3744.23 R2RB_IDL_17_12_TerB54.2@3808.94,-3770.4
  Bot Signal w8: Jbot1.B6@128.26,-3673.77 171.16,-3630.87 845.79,-3630.87 888.27,-3673.35 Jbot2.B6@928.19,-3673.35 ; Jbot2.B6@947.67,-3676.57 990.57,-3633.67 1007.79,-3633.67 1010.59,-3630.87 1662.39,-3630.87 1707.67,-3676.15 1728.19,-3676.15 Jbot3.B6@1747.6,-3676.15 ; Jbot3.B6@1756.27,-3667.32 1799.17,-3624.42 2473.8,-3624.42 2516.28,-3666.9 2528.19,-3666.9 Jbot4.B6@2535.06,-3666.9 ; Jbot4.B6@2528.19,-3673.77 Jbot4.B6@2535.06,-3666.9 ; v1(3731.88,-3710.48) 3727.47,-3710.48 3635.68,-3618.69 3550.68,-3618.69 3536.88,-3632.49 2646.99,-3632.49 2645.79,-3631.29 2570.67,-3631.29 Jbot4.B6@2535.06,-3666.9
JB55: Jbot1.B5 Jbot2.B5 Jbot3.B5 Jbot4.B5 R1RB_IDL_17_12_TerB55.1 R2RB_IDL_17_12_TerB55.2 | length 3881
  Top Signal w8: v1(3678.88,-3710.48) 3785.95,-3817.54 R1RB_IDL_17_12_TerB55.1@3808.43,-3817.54 3808.43,-3843.72 3808.94,-3844.23 R2RB_IDL_17_12_TerB55.2@3808.94,-3870.4
  Bot Signal w8: Jbot1.B5@128.26,-3773.77 171.16,-3730.87 845.79,-3730.87 888.27,-3773.35 Jbot2.B5@928.19,-3773.35 ; Jbot2.B5@947.67,-3776.57 993.37,-3730.87 1645.36,-3730.87 1648.16,-3733.67 1665.19,-3733.67 1707.67,-3776.15 1728.19,-3776.15 Jbot3.B5@1747.6,-3776.15 ; Jbot3.B5@1756.27,-3767.32 1799.17,-3724.42 2473.8,-3724.42 Jbot4.B5@2516.28,-3766.9 ; Jbot4.B5@2528.19,-3773.77 2570.67,-3731.29 2645.79,-3731.29 2656.46,-3741.96 2851.29,-3741.96 2881.61,-3711.65 3677.71,-3711.65 v1(3678.88,-3710.48)
JB56: Jbot1.B4 Jbot2.B4 Jbot3.B4 Jbot4.B4 R1RB_IDL_17_12_TerB56.1 R2RB_IDL_17_12_TerB56.2 | length 3864.3
  Top Signal w8: v1(2839.37,-3923) v1(2839.37,-3923) 3518.55,-3922.96 3523.97,-3917.54 R1RB_IDL_17_12_TerB56.1@3808.43,-3917.54 3808.43,-3943.72 3808.94,-3944.23 R2RB_IDL_17_12_TerB56.2@3808.94,-3970.4
  Bot Signal w8: Jbot1.B4@128.26,-3873.77 171.16,-3830.87 845.79,-3830.87 888.27,-3873.35 Jbot2.B4@928.19,-3873.35 ; Jbot2.B4@947.67,-3876.57 993.37,-3830.87 1645.36,-3830.87 1648.16,-3833.67 1665.19,-3833.67 1707.67,-3876.15 1728.19,-3876.15 Jbot3.B4@1747.6,-3876.15 ; Jbot3.B4@1756.27,-3867.32 1799.17,-3824.42 2473.8,-3824.42 2516.28,-3866.9 2528.19,-3866.9 Jbot4.B4@2556.2,-3866.9 ; Jbot4.B4@2528.19,-3873.77 2570.67,-3916.25 2645.79,-3916.25 2645.92,-3916.11 2832.48,-3916.11 v1(2839.37,-3923)
JB57: Jbot1.B3 Jbot2.B3 Jbot3.B3 Jbot4.B3 R1RB_IDL_17_12_TerB57.1 R2RB_IDL_17_12_TerB57.2 | length 3860.4
  Top Signal w8: v1(3730.54,-4028.52) R1RB_IDL_17_12_TerB57.1@3808.39,-4028.52 3808.39,-4054.72 3808.9,-4055.23 R2RB_IDL_17_12_TerB57.2@3808.9,-4081.38
  Bot Signal w8: Jbot1.B3@128.26,-3973.77 171.16,-3930.87 845.79,-3930.87 888.27,-3973.35 Jbot2.B3@928.19,-3973.35 ; Jbot2.B3@947.67,-3976.57 990.57,-3933.67 1007.79,-3933.67 1010.59,-3930.87 1662.39,-3930.87 1707.67,-3976.15 1728.19,-3976.15 Jbot3.B3@1747.6,-3976.15 ; Jbot3.B3@1756.27,-3967.32 1799.17,-3924.42 2473.8,-3924.42 Jbot4.B3@2516.28,-3966.9 ; Jbot4.B3@2528.19,-3973.77 2571.71,-3930.25 2651.58,-3930.25 2651.72,-3930.11 2669.56,-3930.11 2756.45,-4017 3006.55,-4017 3719.02,-4017 v1(3730.54,-4028.52)
JB58: Jbot1.C32 Jbot2.C32 Jbot3.C32 Jbot4.C32 R1RB_IDL_17_12_TerB58.1 R2RB_IDL_17_12_TerB58.2 | length 4553.1
  Top Signal w8: Jbot1.C32@28.26,-1073.77 70.74,-1031.29 245.86,-1031.29 288.34,-1073.77 827.77,-1073.77 Jbot2.C32@828.19,-1073.35 877.91,-1023.62 1038.55,-1023.62 1070.67,-1055.75 1070.67,-1056.59 1087.85,-1073.77 Jbot3.C32@1628.19,-1073.77 1676.31,-1025.64 1840.14,-1025.64 1888.27,-1073.77 Jbot4.C32@2428.19,-1073.77 ; v1(4276.89,-1052.46) 4332.68,-1108.25 R1RB_IDL_17_12_TerB58.1@4358.16,-1108.25 4358.16,-1134.94 4358.67,-1135.46 R2RB_IDL_17_12_TerB58.2@4358.67,-1161.11
  Bot Signal w8: Jbot4.C32@2428.19,-1073.77 2474.96,-1027 3515,-1027 3527,-1039 4263.43,-1039 v1(4276.89,-1052.46)
JB59: Jbot1.C31 Jbot2.C31 Jbot3.C31 Jbot4.C31 R1RB_IDL_17_12_TerB59.1 R2RB_IDL_17_12_TerB59.2 | length 4554.9
  Top Signal w8: Jbot1.C31@28.26,-1173.77 70.74,-1131.29 245.86,-1131.29 288.34,-1173.77 827.77,-1173.77 Jbot2.C31@828.19,-1173.35 871.74,-1129.8 904.77,-1129.8 ; 904.8,-1129.83 951.58,-1129.83 ; 951.61,-1129.8 1044.72,-1129.8 1070.67,-1155.75 1070.67,-1156.59 1087.85,-1173.77 Jbot3.C31@1628.19,-1173.77 1637.41,-1173.77 1680.03,-1131.15 1863.81,-1131.15 1906.42,-1173.77 Jbot4.C31@2428.19,-1173.77 ; v1(4264.57,-1126.66) 4275.89,-1126.66 4357.48,-1208.25 R1RB_IDL_17_12_TerB59.1@4358.16,-1208.25 4358.16,-1234.94 4358.67,-1235.46 R2RB_IDL_17_12_TerB59.2@4358.67,-1261.11
  Bot Signal w8: Jbot4.C31@2428.19,-1173.77 2485.71,-1116.25 3547.64,-1116.25 3550.68,-1113.2 4251.12,-1113.2 v1(4264.57,-1126.66)
JB60: Jbot1.C30 Jbot2.C30 Jbot3.C30 Jbot4.C30 R1RB_IDL_17_12_TerB60.1 R2RB_IDL_17_12_TerB60.2 | length 4657.1
  Top Signal w8: Jbot1.C30@28.26,-1273.77 70.74,-1231.29 245.86,-1231.29 288.34,-1273.77 827.77,-1273.77 Jbot2.C30@828.19,-1273.35 871.71,-1229.83 1063.2,-1229.83 1107.14,-1273.77 Jbot3.C30@1628.19,-1273.77 1670.67,-1231.29 1845.78,-1231.29 1848.17,-1233.67 1888.27,-1273.77 Jbot4.C30@2428.19,-1273.77 2470.67,-1231.29 2545.78,-1231.29 2550.07,-1235.58 2606.3,-1235.58 2610.59,-1231.29 2645.78,-1231.29 2650.07,-1235.58 2840.49,-1235.58 v1(2864.83,-1211.24) ; v1(4314.68,-1213.46) 4314.68,-1295.25 4332.68,-1313.25 R1RB_IDL_17_12_TerB60.1@4358.16,-1313.25 4358.16,-1339.94 4358.67,-1340.46 R2RB_IDL_17_12_TerB60.2@4358.67,-1366.11
  Bot Signal w8: v1(2864.83,-1211.24) 2869.84,-1216.25 3486.78,-1216.25 3537.33,-1266.8 4261.34,-1266.8 v1(4314.68,-1213.46)
JB61: Jbot1.C29 Jbot2.C29 Jbot3.C29 Jbot4.C29 R1RB_IDL_17_12_TerB61.1 R2RB_IDL_17_12_TerB61.2 | length 4627.4
  Top Signal w8: Jbot1.C29@28.26,-1373.77 70.74,-1331.29 245.86,-1331.29 288.34,-1373.77 827.77,-1373.77 Jbot2.C29@828.19,-1373.35 872.13,-1329.4 904.37,-1329.4 904.8,-1329.83 951.58,-1329.83 952.01,-1329.4 1044.32,-1329.4 1070.67,-1355.75 1070.67,-1356.59 1087.85,-1373.77 Jbot3.C29@1628.19,-1373.77 1668.29,-1333.67 1708.21,-1333.67 1710.59,-1331.29 1845.79,-1331.29 1888.27,-1373.77 Jbot4.C29@2428.19,-1373.77 2428.19,-1363.63 2458.87,-1332.94 2508.94,-1332.94 2510.59,-1331.29 2545.79,-1331.29 2547.44,-1332.94 2592.44,-1332.94 2609.13,-1316.25 3384.25,-1316.25 3401.98,-1298.51 3565.77,-1298.51 3626.65,-1237.64 4182.56,-1237.64 R1RB_IDL_17_12_TerB61.1@4358.16,-1413.25 4358.67,-1413.76 R2RB_IDL_17_12_TerB61.2@4358.67,-1466.11
JB62: Jbot1.C28 Jbot2.C28 Jbot3.C28 Jbot4.C28 R1RB_IDL_17_12_TerB62.1 R2RB_IDL_17_12_TerB62.2 | length 4542.5
  Top Signal w8: Jbot1.C28@28.26,-1473.77 70.74,-1431.29 245.86,-1431.29 288.34,-1473.77 827.77,-1473.77 Jbot2.C28@828.19,-1473.35 869.19,-1432.35 909.11,-1432.35 910.59,-1430.87 1058.1,-1430.87 1101,-1473.77 Jbot3.C28@1628.19,-1473.77 1670.67,-1431.29 1845.78,-1431.29 1848.17,-1433.67 1888.27,-1473.77 Jbot4.C28@2428.19,-1473.77 2470.56,-1431.4 2510.48,-1431.4 2510.59,-1431.29 2545.79,-1431.29 2545.9,-1431.4 2610.48,-1431.4 2610.59,-1431.29 2645.79,-1431.29 2669.5,-1455 v1(2926.95,-1455) ; v1(4153.58,-1513.25) R1RB_IDL_17_12_TerB62.1@4358.16,-1513.25 4358.16,-1539.94 4358.67,-1540.46 R2RB_IDL_17_12_TerB62.2@4358.67,-1566.11
  Bot Signal w8: v1(2926.95,-1455) 3987.7,-1455 3990.1,-1452.61 4092.94,-1452.61 v1(4153.58,-1513.25)
JB63: Jbot1.C27 Jbot2.C27 Jbot3.C27 Jbot4.C27 R1RB_IDL_17_12_TerB63.1 R2RB_IDL_17_12_TerB63.2 | length 4614.9
  Top Signal w8: Jbot1.C27@28.26,-1573.77 70.74,-1531.29 245.86,-1531.29 288.34,-1573.77 827.77,-1573.77 Jbot2.C27@828.19,-1573.35 870.67,-1530.87 1067.85,-1530.87 1110.75,-1573.77 Jbot3.C27@1628.19,-1573.77 1668.29,-1533.67 1708.21,-1533.67 1710.59,-1531.29 1845.79,-1531.29 1888.27,-1573.77 Jbot4.C27@2428.19,-1573.77 ; v1(4181.8,-1613.25) R1RB_IDL_17_12_TerB63.1@4358.16,-1613.25 4358.16,-1639.94 4358.67,-1640.46 R2RB_IDL_17_12_TerB63.2@4358.67,-1666.11
  Bot Signal w8: Jbot4.C27@2428.19,-1573.77 2470.57,-1616.14 2490.37,-1616.14 2491.22,-1617 3469.41,-1617 3517.2,-1664.8 3745.59,-1664.8 3877.95,-1532.44 4100.99,-1532.44 v1(4181.8,-1613.25)
JB64: Jbot1.C26 Jbot2.C26 Jbot3.C26 Jbot4.C26 R1RB_IDL_17_12_TerB64.1 R2RB_IDL_17_12_TerB64.2 | length 4533.8
  Top Signal w8: Jbot1.C26@28.26,-1673.77 70.74,-1631.29 245.86,-1631.29 288.34,-1673.77 827.77,-1673.77 Jbot2.C26@828.19,-1673.35 870.67,-1630.87 1067.85,-1630.87 1110.75,-1673.77 Jbot3.C26@1628.19,-1673.77 1670.67,-1631.29 1845.79,-1631.29 1888.27,-1673.77 Jbot4.C26@2428.19,-1673.77 ; v1(4318.03,-1771.11) R2RB_IDL_17_12_TerB64.2@4358.67,-1771.11 4358.67,-1745.46 4358.16,-1744.94 R1RB_IDL_17_12_TerB64.1@4358.16,-1718.25
  Bot Signal w8: Jbot4.C26@2428.19,-1673.77 2447.99,-1673.77 2504.47,-1730.25 2651.58,-1730.25 2653.55,-1728.28 3549.61,-1728.28 3550.68,-1727.2 3569.56,-1727.2 3570.64,-1728.28 3607.36,-1728.28 3608.44,-1727.2 3751.49,-1727.2 3759.97,-1735.68 3778.86,-1735.68 3779.68,-1734.86 4268.72,-1734.86 4304.97,-1771.11 v1(4318.03,-1771.11)
JB65: Jbot1.C25 Jbot2.C25 Jbot3.C25 Jbot4.C25 R1RB_IDL_17_12_TerB65.1 R2RB_IDL_17_12_TerB65.2 | length 4551.4
  Top Signal w8: Jbot1.C25@28.26,-1773.77 70.74,-1731.29 245.86,-1731.29 288.34,-1773.77 827.77,-1773.77 Jbot2.C25@828.19,-1773.35 870.67,-1730.87 1045.78,-1730.87 1088.68,-1773.77 Jbot3.C25@1628.19,-1773.77 1668.29,-1733.67 1708.21,-1733.67 1710.59,-1731.29 1845.79,-1731.29 1888.27,-1773.77 Jbot4.C25@2428.19,-1773.77 ; v1(3728.75,-1798.89) 3797.14,-1798.89 3805.93,-1790.09 4204.67,-1790.09 4285.68,-1871.11 R2RB_IDL_17_12_TerB65.2@4358.67,-1871.11 4358.67,-1845.46 4358.16,-1844.94 R1RB_IDL_17_12_TerB65.1@4358.16,-1818.25
  Bot Signal w8: Jbot4.C25@2428.19,-1773.77 2442.83,-1788.41 2482.76,-1788.41 2510.59,-1816.25 2645.79,-1816.25 2655.59,-1806.44 3721.19,-1806.44 v1(3728.75,-1798.89)
JB66: Jbot1.C24 Jbot2.C24 Jbot3.C24 Jbot4.C24 R1RB_IDL_17_12_TerB66.1 R2RB_IDL_17_12_TerB66.2 | length 4544.2
  Top Signal w8: Jbot1.C24@28.26,-1873.77 70.74,-1831.29 245.86,-1831.29 288.34,-1873.77 827.77,-1873.77 Jbot2.C24@828.19,-1873.35 870.67,-1830.87 1045.78,-1830.87 1088.68,-1873.77 Jbot3.C24@1628.19,-1873.77 1670.67,-1831.29 1845.78,-1831.29 1848.17,-1833.67 1888.27,-1873.77 Jbot4.C24@2428.19,-1873.77 2468.11,-1873.77 2510.59,-1831.29 2545.79,-1831.29 2546.54,-1832.04 2609.84,-1832.04 2610.59,-1831.29 2645.79,-1831.29 2669.01,-1854.51 v1(2837.76,-1854.51) ; v1(4114.21,-1900.46) 4340.37,-1900.46 R1RB_IDL_17_12_TerB66.1@4358.16,-1918.25 4358.16,-1944.94 4358.67,-1945.46 R2RB_IDL_17_12_TerB66.2@4358.67,-1971.11
  Bot Signal w8: v1@2838.52,-1853.75 v1(2837.76,-1854.51) 2837.86,-1854.62 3864.33,-1854.62 3891.82,-1882.1 4095.86,-1882.1 v1(4114.21,-1900.46)
JB67: Jbot1.C23 Jbot2.C23 Jbot3.C23 Jbot4.C23 R1RB_IDL_17_12_TerB67.1 R2RB_IDL_17_12_TerB67.2 | length 4543.3
  Top Signal w8: Jbot1.C23@28.26,-1973.77 70.74,-1931.29 245.86,-1931.29 288.34,-1973.77 827.77,-1973.77 Jbot2.C23@828.19,-1973.35 870.67,-1930.87 1045.78,-1930.87 1088.68,-1973.77 Jbot3.C23@1628.19,-1973.77 1670.67,-1931.29 1845.78,-1931.29 1847.89,-1933.39 1888.27,-1973.77 Jbot4.C23@2428.19,-1973.77 2470.67,-1931.29 2645.79,-1931.29 2668.91,-1954.41 v1(2854.88,-1954.41) ; v1(4236.93,-2020.25) R1RB_IDL_17_12_TerB67.1@4358.16,-2020.25 4358.16,-2046.94 4358.67,-2047.46 R2RB_IDL_17_12_TerB67.2@4358.67,-2073.11
  Bot Signal w8: v1(2854.88,-1954.41) 2857.26,-1956.8 3639.31,-1956.8 3690.95,-2008.44 4225.12,-2008.44 v1(4236.93,-2020.25)
JB68: Jbot1.C22 Jbot2.C22 Jbot3.C22 Jbot4.C22 R1RB_IDL_17_12_TerB68.1 R2RB_IDL_17_12_TerB68.2 | length 4547.1
  Top Signal w8: Jbot1.C22@28.26,-2073.77 70.74,-2031.29 245.86,-2031.29 288.34,-2073.77 827.77,-2073.77 Jbot2.C22@828.19,-2073.35 870.67,-2030.87 1065.32,-2030.87 1108.22,-2073.77 Jbot3.C22@1628.19,-2073.77 1668.57,-2033.39 1708.49,-2033.39 1710.59,-2031.29 1845.79,-2031.29 1888.27,-2073.77 Jbot4.C22@2428.19,-2073.77 ; v1(4061.76,-2095.07) 4091.94,-2125.25 R1RB_IDL_17_12_TerB68.1@4358.16,-2125.25 4358.16,-2151.94 4358.67,-2152.46 R2RB_IDL_17_12_TerB68.2@4358.67,-2178.11
  Bot Signal w8: Jbot4.C22@2428.19,-2073.77 2470.67,-2031.29 2565.91,-2031.29 2567.9,-2033.28 2608.6,-2033.28 2610.59,-2031.29 2645.79,-2031.29 2667.5,-2053 3418.44,-2053 3435.35,-2069.9 4036.59,-2069.9 v1(4061.76,-2095.07)
JB69: Jbot1.C21 Jbot2.C21 Jbot3.C21 Jbot4.C21 R1RB_IDL_17_12_TerB69.1 R2RB_IDL_17_12_TerB69.2 | length 4579.4
  Top Signal w8: Jbot1.C21@28.26,-2173.77 70.74,-2131.29 245.86,-2131.29 288.34,-2173.77 827.77,-2173.77 Jbot2.C21@828.19,-2173.35 870.67,-2130.87 1045.78,-2130.87 1048.52,-2133.6 1078.17,-2133.6 1118.34,-2173.77 Jbot3.C21@1628.19,-2173.77 1670.67,-2131.29 1845.78,-2131.29 1847.89,-2133.39 1888.27,-2173.77 Jbot4.C21@2428.19,-2173.77 2470.67,-2131.29 2880.68,-2131.29 v1(2881.32,-2130.64) ; v1(4277.68,-2210.46) 4291.02,-2210.46 R2RB_IDL_17_12_TerB69.2@4358.67,-2278.11 4358.67,-2225.76 R1RB_IDL_17_12_TerB69.1@4358.16,-2225.25
  Bot Signal w8: v1(2881.32,-2130.64) 2892.69,-2119.28 3944.38,-2119.28 3946.32,-2117.34 3965.21,-2117.34 4006.17,-2158.31 4225.53,-2158.31 v1(4277.68,-2210.46)
JB70: Jbot1.C20 Jbot2.C20 Jbot3.C20 Jbot4.C20 R1RB_IDL_17_12_TerB70.1 R2RB_IDL_17_12_TerB70.2 | length 4559.1
  Top Signal w8: Jbot1.C20@28.26,-2273.77 70.74,-2231.29 245.86,-2231.29 288.34,-2273.77 827.77,-2273.77 Jbot2.C20@828.19,-2273.35 870.67,-2230.87 1068.94,-2230.87 1111.84,-2273.77 Jbot3.C20@1628.19,-2273.77 1670.67,-2231.29 1845.78,-2231.29 1847.89,-2233.39 1888.27,-2273.77 Jbot4.C20@2428.19,-2273.77 2470.67,-2231.29 2645.79,-2231.29 2665.98,-2251.48 v1(2893.87,-2251.48) ; v1(4309.43,-2325.25) R1RB_IDL_17_12_TerB70.1@4358.16,-2325.25 R1RB_IDL_17_12_TerB70.1@4358.16,-2328.16 ; R1RB_IDL_17_12_TerB70.1@4353.52,-2332.8 R1RB_IDL_17_12_TerB70.1@4358.16,-2328.16 ; R2RB_IDL_17_12_TerB70.2@4358.67,-2378.11 4358.16,-2344.46 R1RB_IDL_17_12_TerB70.1@4358.16,-2328.16
  Bot Signal w8: v1(2893.87,-2251.48) 3507.37,-2251.48 3534.68,-2278.8 3940.75,-2278.8 3949.63,-2269.92 4254.1,-2269.92 v1(4309.43,-2325.25)
JB71: Jbot1.C19 Jbot2.C19 Jbot3.C19 Jbot4.C19 R1RB_IDL_17_12_TerB71.1 R2RB_IDL_17_12_TerB71.2 | length 4670
  Top Signal w8: Jbot1.C19@28.26,-2373.77 70.74,-2331.29 245.86,-2331.29 288.34,-2373.77 827.77,-2373.77 Jbot2.C19@828.19,-2373.35 870.67,-2330.87 1083.75,-2330.87 1126.65,-2373.77 Jbot3.C19@1628.19,-2373.77 1670.67,-2331.29 1845.78,-2331.29 1847.89,-2333.39 1888.27,-2373.77 Jbot4.C19@2428.19,-2373.77 2470.67,-2331.29 2684.49,-2331.29 2710.81,-2304.96 3535.4,-2304.96 3659.4,-2180.96 3933.59,-2180.96 3933.63,-2180.92 3952.51,-2180.92 3966.01,-2194.42 4127.33,-2194.42 R1RB_IDL_17_12_TerB71.1@4358.16,-2425.25 4358.16,-2451.94 4358.67,-2452.46 R2RB_IDL_17_12_TerB71.2@4358.67,-2478.11
JB72: Jbot1.C18 Jbot2.C18 Jbot3.C18 Jbot4.C18 R1RB_IDL_17_12_TerB72.1 R2RB_IDL_17_12_TerB72.2 | length 4546.2
  Top Signal w8: Jbot1.C18@28.26,-2473.77 70.74,-2431.29 245.86,-2431.29 288.34,-2473.77 827.77,-2473.77 Jbot2.C18@828.19,-2473.35 870.67,-2430.87 1066.77,-2430.87 1109.67,-2473.77 Jbot3.C18@1628.19,-2473.77 1668.57,-2433.39 1708.49,-2433.39 1710.59,-2431.29 1845.79,-2431.29 1888.27,-2473.77 Jbot4.C18@2428.19,-2473.77 2469.72,-2432.24 2509.64,-2432.24 2510.59,-2431.29 2545.79,-2431.29 2546.74,-2432.24 2609.64,-2432.24 2610.59,-2431.29 2645.79,-2431.29 2677.07,-2462.57 v1(2915.11,-2462.57) ; v1(3978.02,-2495.92) 4007.35,-2525.25 R1RB_IDL_17_12_TerB72.1@4358.16,-2525.25 4358.16,-2551.94 4358.67,-2552.46 R2RB_IDL_17_12_TerB72.2@4358.67,-2578.11
  Bot Signal w8: v1(2915.11,-2462.57) 2915.54,-2463 3758.15,-2463 3791.07,-2495.92 v1(3978.02,-2495.92)
JB73: Jbot1.C17 Jbot2.C17 Jbot3.C17 Jbot4.C17 R1RB_IDL_17_12_TerB73.1 R2RB_IDL_17_12_TerB73.2 | length 4522.9
  Top Signal w8: Jbot1.C17@28.26,-2573.77 70.74,-2531.29 245.86,-2531.29 288.34,-2573.77 827.77,-2573.77 Jbot2.C17@828.19,-2573.35 870.67,-2530.87 1062.07,-2530.87 1104.97,-2573.77 Jbot3.C17@1628.19,-2573.77 1670.67,-2531.29 1845.78,-2531.29 1847.89,-2533.39 1888.27,-2573.77 Jbot4.C17@2428.19,-2573.77 ; v1(2853.8,-2613.34) 3400.16,-2613.34 3403.54,-2609.96 3518.55,-2609.96 3525.08,-2603.44 4188.41,-2603.44 4215.23,-2630.25 R1RB_IDL_17_12_TerB73.1@4358.16,-2630.25 4358.16,-2656.94 4358.67,-2657.46 R2RB_IDL_17_12_TerB73.2@4358.67,-2683.11
  Bot Signal w8: Jbot4.C17@2428.19,-2573.77 2457.47,-2573.77 2499.95,-2616.25 2850.89,-2616.25 v1(2853.8,-2613.34)
JB74: Jbot1.C16 Jbot2.C16 Jbot3.C16 Jbot4.C16 R1RB_IDL_17_12_TerB74.1 R2RB_IDL_17_12_TerB74.2 | length 4608.1
  Top Signal w8: Jbot1.C16@28.26,-2673.77 70.74,-2631.29 245.86,-2631.29 287.92,-2673.35 Jbot2.C16@828.19,-2673.35 828.19,-2662.25 859.57,-2630.87 1045.79,-2630.87 1088.27,-2673.35 1608.49,-2673.35 1618.13,-2663.7 1650.55,-2631.29 2385.71,-2631.29 Jbot4.C16@2428.19,-2673.77 2470.67,-2631.29 2645.79,-2631.29 2664.14,-2649.64 v1(2916.16,-2649.64) ; v1(4315.57,-2692.8) 4355.59,-2732.82 4356.82,-2734.05 4358.16,-2750.98 ; R1RB_IDL_17_12_TerB74.1@4358.16,-2730.25 4358.16,-2750.98 ; 4358.16,-2750.98 4360.69,-2782.95 4360.88,-2785.31 R2RB_IDL_17_12_TerB74.2@4358.67,-2783.11 4358.16,-2782.6 4358.16,-2750.98
  Bot Signal w8: v1(2916.16,-2649.64) 3494.17,-2649.64 3528.97,-2684.44 3968.51,-2684.44 3976.87,-2692.8 v1(4315.57,-2692.8)
JB75: Jbot1.C15 Jbot2.C15 Jbot3.C15 Jbot4.C15 R1RB_IDL_17_12_TerB75.1 R2RB_IDL_17_12_TerB75.2 | length 4595.1
  Top Signal w8: Jbot1.C15@28.26,-2773.77 70.74,-2731.29 245.86,-2731.29 287.92,-2773.35 Jbot2.C15@828.19,-2773.35 870.67,-2730.87 1071.16,-2730.87 1113.64,-2773.35 1627.77,-2773.35 Jbot3.C15@1628.19,-2773.77 1673.84,-2728.12 1702.67,-2728.12 1704.79,-2730.25 1751.58,-2730.25 1753.71,-2728.12 2382.54,-2728.12 Jbot4.C15@2428.19,-2773.77 ; v1(4179.33,-2830.25) R1RB_IDL_17_12_TerB75.1@4358.16,-2830.25 4358.16,-2856.94 4358.67,-2857.46 R2RB_IDL_17_12_TerB75.2@4358.67,-2883.11
  Bot Signal w8: Jbot4.C15@2428.19,-2773.77 2442.94,-2773.77 2487.26,-2818.08 2604,-2818.08 2604.8,-2817.29 2651.58,-2817.29 2652.38,-2818.08 2747.11,-2818.08 2822.66,-2742.54 3413.54,-2742.54 3520,-2849 4160.58,-2849 v1(4179.33,-2830.25)
JB76: Jbot1.C14 Jbot2.C14 Jbot3.C14 Jbot4.C14 R1RB_IDL_17_12_TerB76.1 R2RB_IDL_17_12_TerB76.2 | length 4520.8
  Top Signal w8: Jbot1.C14@28.26,-2873.77 70.74,-2831.29 245.86,-2831.29 287.92,-2873.35 Jbot2.C14@828.19,-2873.35 870.67,-2830.87 1061.41,-2830.87 1103.89,-2873.35 1627.77,-2873.35 Jbot3.C14@1628.19,-2873.77 1668.11,-2873.77 1710.59,-2831.29 1750.99,-2831.29 1752.47,-2829.8 1844.3,-2829.8 1888.27,-2873.77 Jbot4.C14@2428.19,-2873.77 ; v1(2821.33,-2916.52) 3401.98,-2916.52 3802.76,-2916.51 3825.67,-2939.42 4348.99,-2939.42 R1RB_IDL_17_12_TerB76.1@4358.16,-2930.25 4358.16,-2956.94 4358.67,-2957.46 R2RB_IDL_17_12_TerB76.2@4358.67,-2983.11
  Bot Signal w8: Jbot4.C14@2428.19,-2873.77 2470.94,-2916.52 v1(2821.33,-2916.52)
JB77: Jbot1.C13 Jbot2.C13 Jbot3.C13 Jbot4.C13 R1RB_IDL_17_12_TerB77.1 R2RB_IDL_17_12_TerB77.2 | length 4550.1
  Top Signal w8: Jbot1.C13@28.26,-2973.77 70.74,-2931.29 245.86,-2931.29 287.92,-2973.35 Jbot2.C13@828.19,-2973.35 870.67,-2930.87 1067.91,-2930.87 1110.39,-2973.35 1627.77,-2973.35 Jbot3.C13@1628.19,-2973.77 1671.71,-2930.25 2384.67,-2930.25 Jbot4.C13@2428.19,-2973.77 2470.67,-2931.29 2645.79,-2931.29 2655.2,-2940.7 v1(2971.76,-2940.7) ; v1(4096.79,-3035.25) R1RB_IDL_17_12_TerB77.1@4358.16,-3035.25 4358.16,-3061.94 4358.67,-3062.46 R2RB_IDL_17_12_TerB77.2@4358.67,-3088.11
  Bot Signal w8: v1(2971.76,-2940.7) 3524.86,-2940.7 3548.24,-2964.07 4025.61,-2964.07 v1(4096.79,-3035.25)
JB78: Jbot1.C12 Jbot2.C12 Jbot3.C12 Jbot4.C12 R1RB_IDL_17_12_TerB78.1 R2RB_IDL_17_12_TerB78.2 | length 4569.5
  Top Signal w8: Jbot1.C12@28.26,-3073.77 70.74,-3031.29 245.86,-3031.29 287.92,-3073.35 Jbot2.C12@828.19,-3073.35 870.67,-3030.87 1062.13,-3030.87 1104.61,-3073.35 1627.77,-3073.35 Jbot3.C12@1628.19,-3073.77 1671.99,-3029.97 1704.52,-3029.97 1704.8,-3030.25 1751.58,-3030.25 1751.86,-3029.97 1844.47,-3029.97 1888.27,-3073.77 Jbot4.C12@2428.19,-3073.77 ; v1(4151.68,-3135.25) R1RB_IDL_17_12_TerB78.1@4358.16,-3135.25 4358.67,-3135.76 R2RB_IDL_17_12_TerB78.2@4358.67,-3188.11
  Bot Signal w8: Jbot4.C12@2428.19,-3073.77 2470.67,-3031.29 2967.69,-3031.29 2978.45,-3042.05 3220.99,-3042.05 3243.9,-3019.15 4035.58,-3019.15 v1(4151.68,-3135.25)
JB79: Jbot1.C11 Jbot2.C11 Jbot3.C11 Jbot4.C11 R1RB_IDL_17_12_TerB79.1 R2RB_IDL_17_12_TerB79.2 | length 4617.8
  Top Signal w8: Jbot1.C11@28.26,-3173.77 70.74,-3131.29 245.86,-3131.29 287.92,-3173.35 Jbot2.C11@828.19,-3173.35 870.67,-3130.87 1069.53,-3130.87 1111.84,-3173.17 1111.84,-3173.35 1627.77,-3173.35 Jbot3.C11@1628.19,-3173.77 1672.34,-3129.61 1704.16,-3129.61 1704.8,-3130.25 1751.58,-3130.25 1752.22,-3129.61 2384.04,-3129.61 Jbot4.C11@2428.19,-3173.77 2470.67,-3131.29 2827.29,-3131.29 v1(2835.72,-3122.86) ; v1(4298.99,-3244.35) 4349.06,-3244.35 R1RB_IDL_17_12_TerB79.1@4358.16,-3235.25 4358.16,-3287.6 R2RB_IDL_17_12_TerB79.2@4358.67,-3288.11
  Bot Signal w8: v1(2835.72,-3122.86) 2898.54,-3060.04 3568.4,-3060.04 3587.18,-3078.82 4062.43,-3078.82 4227.97,-3244.35 v1(4298.99,-3244.35)
JB80: Jbot1.C10 Jbot2.C10 Jbot3.C10 Jbot4.C10 R1RB_IDL_17_12_TerB80.1 R2RB_IDL_17_12_TerB80.2 | length 4570.5
  Top Signal w8: Jbot1.C10@28.26,-3273.77 70.74,-3231.29 245.86,-3231.29 287.92,-3273.35 Jbot2.C10@828.19,-3273.35 870.67,-3230.87 1060.69,-3230.87 1103.17,-3273.35 1627.77,-3273.35 Jbot3.C10@1628.19,-3273.77 1671.99,-3229.97 1704.52,-3229.97 1704.8,-3230.25 1751.58,-3230.25 1751.86,-3229.97 1844.47,-3229.97 1888.27,-3273.77 Jbot4.C10@2428.19,-3273.77 ; v1(4288.68,-3335.25) R1RB_IDL_17_12_TerB80.1@4358.16,-3335.25 4358.16,-3387.6 R2RB_IDL_17_12_TerB80.2@4358.67,-3388.11
  Bot Signal w8: Jbot4.C10@2428.19,-3273.77 2442.94,-3273.77 2486.18,-3317 2486.93,-3316.25 2679.84,-3316.25 2705.3,-3290.8 3569.56,-3290.8 3609.92,-3250.44 4203.87,-3250.44 v1(4288.68,-3335.25)
JB81: Jbot1.C9 Jbot2.C9 Jbot3.C9 Jbot4.C9 R1RB_IDL_17_12_TerB81.1 R2RB_IDL_17_12_TerB81.2 | length 4603.5
  Top Signal w8: Jbot1.C9@28.26,-3373.77 70.74,-3331.29 245.86,-3331.29 287.92,-3373.35 Jbot2.C9@828.19,-3373.35 868.69,-3332.84 908.62,-3332.84 910.59,-3330.87 1062.85,-3330.87 1105.33,-3373.35 1627.77,-3373.35 Jbot3.C9@1628.19,-3373.77 1671.99,-3329.97 1704.52,-3329.97 1704.79,-3330.25 1751.58,-3330.25 1751.86,-3329.97 1844.47,-3329.97 1888.27,-3373.77 Jbot4.C9@2428.19,-3373.77 ; v1(4213.24,-3360.4) 4209.54,-3364.11 4285.68,-3440.25 R1RB_IDL_17_12_TerB81.1@4358.16,-3440.25 4358.16,-3466.94 4358.67,-3467.46 R2RB_IDL_17_12_TerB81.2@4358.67,-3493.11
  Bot Signal w8: Jbot4.C9@2428.19,-3373.77 2442.94,-3373.77 2485.43,-3416.25 2645.79,-3416.25 2740.75,-3321.28 3565.77,-3321.28 3586.93,-3342.44 3963.51,-3342.44 3981.48,-3360.4 v1(4213.24,-3360.4)
JB82: Jbot1.C8 Jbot2.C8 Jbot3.C8 Jbot4.C8 R1RB_IDL_17_12_TerB82.1 R2RB_IDL_17_12_TerB82.2 | length 4546.5
  Top Signal w8: Jbot1.C8@28.26,-3473.77 70.74,-3431.29 245.86,-3431.29 287.92,-3473.35 Jbot2.C8@828.19,-3473.35 870.67,-3430.87 1075.14,-3430.87 1117.62,-3473.35 1627.77,-3473.35 Jbot3.C8@1628.19,-3473.77 1671.99,-3429.97 1704.52,-3429.97 1704.8,-3430.25 1751.58,-3430.25 1751.86,-3429.97 1869.72,-3429.97 1913.52,-3473.77 Jbot4.C8@2428.19,-3473.77 ; v1(4137.6,-3543.46) R1RB_IDL_17_12_TerB82.1@4358.16,-3543.46 ; R1RB_IDL_17_12_TerB82.1@4358.16,-3542.25 R1RB_IDL_17_12_TerB82.1@4358.16,-3543.46 ; R2RB_IDL_17_12_TerB82.2@4358.67,-3595.11 4358.16,-3568.94 R1RB_IDL_17_12_TerB82.1@4358.16,-3543.46
  Bot Signal w8: Jbot4.C8@2428.19,-3473.77 2455.15,-3473.77 2512.67,-3531.29 2645.79,-3531.29 2665.7,-3551.2 3591.99,-3551.2 3617.94,-3577.16 4103.89,-3577.16 v1(4137.6,-3543.46)
JB83: Jbot1.C7 Jbot2.C7 Jbot3.C7 Jbot4.C7 R1RB_IDL_17_12_TerB83.1 R2RB_IDL_17_12_TerB83.2 | length 4563.4
  Top Signal w8: Jbot1.C7@28.26,-3573.77 70.74,-3531.29 245.86,-3531.29 287.92,-3573.35 Jbot2.C7@828.19,-3573.35 871.62,-3529.92 1044.84,-3529.92 1088.27,-3573.35 1608.49,-3573.35 1618.13,-3563.7 1650.55,-3531.29 1845.79,-3531.29 1888.27,-3573.77 Jbot4.C7@2428.19,-3573.77 2470.67,-3531.29 2610.59,-3531.29 2620.76,-3521.12 2800.73,-3521.12 2803.47,-3523.87 2806.45,-3526.84 v1(2806.45,-3520.89) ; v1(4299.9,-3645.48) 4354.93,-3645.48 R1RB_IDL_17_12_TerB83.1@4358.16,-3642.25 4358.16,-3694.6 R2RB_IDL_17_12_TerB83.2@4358.67,-3695.11
  Bot Signal w8: v1@2815.7,-3521.75 2816.79,-3520.66 4175.08,-3520.66 v1(4299.9,-3645.48)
